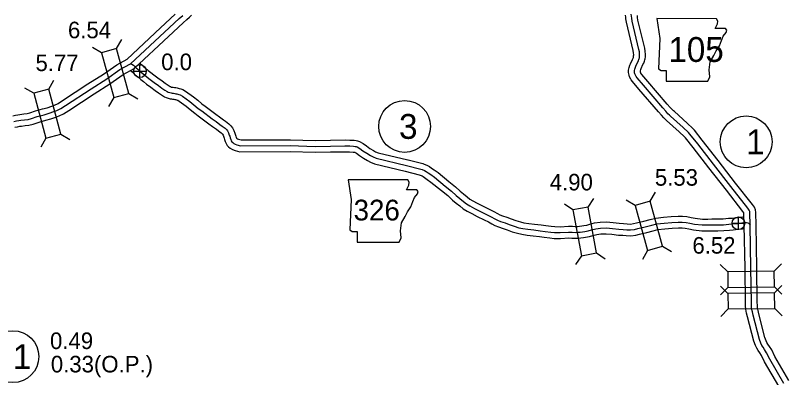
# Model space of a CAD drawing. Extents: x 31699 to 244310, y -8841 to 11474.
# Drawn here: x 97253 to 98557, y 4320 to 4936 of the extents above; entities that cross this region are included whole.
import ezdxf

# ---------------------------------------------------------------- set-up
doc = ezdxf.new("R2010")
doc.units = 0
for name, color, linetype in [('B_Logo', 7, 'Continuous'), ('G-ANNO-TEXT', 7, 'Continuous'), ('Level 21', 7, 'Continuous'), ('R_Border Notes', 7, 'Continuous'), ('R_XS_EARTHWORK_STAGE1', 7, 'Continuous'), ('R_XS_EARTHWORK_STAGE2', 7, 'Continuous'), ('S_WALL', 7, 'Continuous'), ('S_WALL_ANNOT', 7, 'Continuous')]:
    doc.layers.add(name, color=color, linetype=linetype)

msp = doc.modelspace()

# ---------------------------------------------------------------- linework, layer by layer
at = {"layer": 'B_Logo'}
for points in [[(97250.1, 4755.6), (97254.7, 4756.5), (97258.7, 4757.3), (97261.9, 4757.8), (97268.4, 4758.7), (97274.4, 4759.1), (97280.3, 4760.5), (97289.8, 4764), (97301.7, 4767.2), (97310, 4769.5), (97318, 4772.3), (97323.2, 4774.4), (97330, 4777.4), (97338.1, 4782.7), (97381.5, 4811), (97407.9, 4827.8), (97430.5, 4843.7), (97448.4, 4853.6), (97506.1, 4907.4), (97531.3, 4930.6), (97537.2, 4935.9)], [(98300.2, 4934.6), (98299.7, 4937.8)], [(98559.1, 4310.6), (98535.1, 4351.8), (98529.7, 4362.6), (98526.4, 4368), (98523.7, 4372.1), (98521.7, 4375.3), (98519.8, 4378.9), (98517.4, 4385.4), (98506.9, 4426.4), (98505.5, 4432.1), (98504.3, 4437.8), (98504.1, 4442.3), (98503.8, 4448.1), (98503.1, 4506.6), (98501.8, 4579.3), (98501.3, 4600.5), (98501, 4602.8), (98500.1, 4605), (98497.6, 4608.6), (98469.2, 4644.9), (98439.4, 4683.3), (98412.6, 4717.6), (98399.4, 4734.2), (98397, 4736.8), (98387.9, 4745.2), (98366.3, 4764.8), (98364.6, 4766.4), (98362, 4768.8), (98358.5, 4772.9), (98353.3, 4778.7), (98320.2, 4817.3), (98309.5, 4829.7), (98307.9, 4832.1), (98307.3, 4832.9), (98306.1, 4835.3), (98305.6, 4836.8), (98305.4, 4838.2), (98305.2, 4839.7), (98305, 4842.2), (98305.5, 4844.6), (98306.7, 4847.8), (98307.5, 4849.6), (98310.6, 4856.7), (98311.7, 4858.8), (98312.7, 4861.2), (98313.1, 4862.9), (98313.4, 4863.9), (98313.7, 4866.5), (98313.9, 4869), (98313.4, 4873.7), (98312.7, 4878.1), (98301.2, 4925.9), (98300.6, 4931.1), (98300.2, 4934.6)], [(97448.4, 4853.6), (97450.7, 4852.8), (97453.3, 4851.4), (97455.2, 4849.8), (97458.1, 4847), (97460.8, 4844.5), (97463.1, 4842.1), (97467, 4839), (97472.3, 4834.7), (97476.7, 4831.1), (97481.9, 4827), (97488.8, 4821.9), (97496.2, 4816.5), (97501.8, 4812.5), (97506.7, 4809), (97510.9, 4806.3), (97512.6, 4805.5), (97515.4, 4804.6), (97517.4, 4804.1), (97519.4, 4803.9), (97521.5, 4803.5), (97523.5, 4803.2), (97525.5, 4802.8), (97527, 4802.5), (97528.9, 4802), (97530.8, 4801.6), (97533.1, 4800.7), (97536.6, 4798.8), (97549.4, 4789.5), (97556.2, 4783.9), (97563.6, 4777.9), (97569.4, 4773.5), (97587.5, 4759.9), (97593.8, 4755.4), (97600.5, 4750.6), (97604.1, 4747.9), (97609.1, 4744.1), (97611.6, 4741.8), (97613.4, 4739.5), (97615, 4736.5), (97616.3, 4732.6), (97617, 4730.9), (97617.9, 4728), (97618.8, 4724.9), (97619.6, 4723), (97620.7, 4721.3), (97622.1, 4719.8), (97623.8, 4718.3), (97626.2, 4716.8), (97629.3, 4715.7), (97635.5, 4714.2), (97720.1, 4714.7), (97762.3, 4713.4), (97788.4, 4713.8), (97813, 4714.2), (97821.1, 4714.1), (97827.6, 4713.6), (97830.4, 4713.3), (97832.1, 4713), (97834, 4712.5), (97838.4, 4710), (97843.5, 4705.9), (97850.1, 4701.6), (97856.3, 4697.7), (97860.7, 4695.3), (97866.1, 4693.1), (97917.8, 4681)], [(97917.8, 4681), (97942.2, 4674.6), (97944.3, 4673.9), (97948.4, 4672.2), (97951.3, 4670.9), (97954.2, 4668.5), (97958.7, 4665.3), (97965.1, 4660.8), (97983.4, 4645.9), (97994.1, 4637.2), (98002.3, 4629.6), (98008.3, 4624.9), (98014.5, 4619.8), (98019.5, 4615.5), (98025.5, 4612.1), (98033.2, 4607.9), (98042.4, 4603.2), (98053.8, 4597.8), (98061.5, 4593.8), (98067.7, 4590.5), (98072.2, 4588.1), (98077.5, 4585.9), (98085.1, 4583.4), (98092, 4580.7), (98100.5, 4577.9), (98108.8, 4575.2), (98115.3, 4573.7), (98124.1, 4572.5), (98134.1, 4571.5), (98145.1, 4569.9), (98153.1, 4568.9), (98162.7, 4567.7), (98169.1, 4567), (98179, 4566.9), (98193.2, 4567.7), (98199, 4567.5), (98204.3, 4567.2), (98209.4, 4567.3), (98212.8, 4567.6), (98217, 4568.4), (98220.6, 4568.8), (98226.5, 4569.9), (98231.8, 4571.4), (98239.3, 4573.5), (98247.4, 4574.6), (98257.4, 4574.9), (98267.8, 4573.9), (98278.5, 4572.6), (98286.1, 4572.3), (98291.9, 4571.8), (98298.4, 4571.3), (98305.4, 4572.2), (98311.1, 4573.6), (98323.4, 4576.6), (98334.4, 4579.6), (98343.1, 4581.7), (98355.7, 4583), (98368.5, 4584.1), (98379.5, 4584.8), (98386.4, 4584.7), (98392.8, 4584.2), (98399.5, 4582.9), (98406.9, 4581.4), (98420.3, 4579.9), (98429.7, 4579.9), (98436.8, 4580), (98446.6, 4580), (98456.4, 4580.3), (98465.5, 4581.2), (98471.9, 4581.7), (98476.1, 4582.1), (98481.4, 4582.5), (98484.7, 4583), (98487.4, 4583.3), (98490.5, 4583.7), (98492.6, 4583.8), (98494.3, 4583.9), (98495.7, 4583.9), (98497.7, 4583.5), (98498.8, 4582.9), (98499.7, 4582.4), (98500.3, 4581.5), (98500.8, 4581), (98501.8, 4579.3)]]:
    msp.add_lwpolyline(points, dxfattribs=at)
at = {"layer": 'G-ANNO-TEXT'}
for points in [[(98343, 4930.3), (98348.1, 4896.5), (98345.8, 4845.1), (98350.4, 4842.3), (98358.8, 4842.3), (98358.8, 4824.3), (98429.9, 4824.3), (98433.3, 4831.6), (98432.1, 4843.4), (98433.8, 4857), (98440, 4867.7), (98444, 4875.6), (98449.6, 4884.1), (98453, 4893.1), (98455.8, 4900.4), (98460.9, 4906.6), (98462, 4910.6), (98459.8, 4913.4), (98442.3, 4913.4), (98446.2, 4921.3), (98446.8, 4926.3), (98444.4, 4930.2)], [(97818.2, 4656.6), (97823.3, 4622.8), (97821, 4571.5), (97825.5, 4568.6), (97834, 4568.6), (97834, 4550.6), (97905, 4550.6), (97908.4, 4557.9), (97907.3, 4569.8), (97909, 4583.3), (97915.2, 4594), (97919.1, 4601.9), (97924.8, 4610.4), (97928.2, 4619.4), (97931, 4626.7), (97936.1, 4632.9), (97937.2, 4636.9), (97934.9, 4639.7), (97917.5, 4639.7), (97921.4, 4647.6), (97922, 4652.7), (97919.6, 4656.6)]]:
    msp.add_lwpolyline(points, close=True, dxfattribs=at)
at = {"layer": 'Level 21'}
for p, q in [((97453.5, 4841.1), (97475.2, 4841.1)), ((97464.4, 4830.2), (97464.4, 4851.9)), ((98481.8, 4572), (98481.8, 4593.7)), ((98470.9, 4582.8), (98492.6, 4582.8))]:
    msp.add_line(p, q, dxfattribs=at)
for centre in [(97464.4, 4841.1), (98481.8, 4582.8)]:
    msp.add_circle(centre, 10.8, dxfattribs=at)
at = {"layer": 'R_Border Notes'}
for centre in [(97914.4, 4747.2), (98495, 4721), (97248.6, 4356.1)]:
    msp.add_circle(centre, 44, dxfattribs=at)
at = {"layer": 'R_XS_EARTHWORK_STAGE1'}
for p, q in [((97424.6, 4879.4), (97433.4, 4894.7)), ((97399.2, 4872.5), (97383.9, 4881.3)), ((97309.5, 4810.4), (97318.2, 4825.6)), ((97284, 4803.5), (97268.7, 4812.2)), ((97445.3, 4803), (97460.6, 4794.2)), ((97419.9, 4796.1), (97411.1, 4780.8)), ((97304.7, 4727), (97295.9, 4711.8)), ((97330.2, 4733.9), (97345.4, 4725.2)), ((98331.9, 4620), (98340.6, 4635.3)), ((98226.3, 4610.1), (98236.3, 4624.7)), ((98306.5, 4613), (98291.2, 4621.7)), ((98200.4, 4605.3), (98185.9, 4615.2)), ((98352.8, 4543.6), (98368.1, 4534.9)), ((98214.9, 4527.4), (98204.9, 4512.9)), ((98240.8, 4532.3), (98255.4, 4522.3)), ((98327.4, 4536.6), (98318.6, 4521.3)), ((98542.8, 4501.1), (98555.1, 4513.7)), ((98463.6, 4500.2), (98451, 4512.5)), ((98464, 4463.5), (98451.4, 4475.8)), ((98543.1, 4474.7), (98555.7, 4462.4)), ((98543.2, 4464.4), (98555.5, 4477)), ((98463.9, 4473.8), (98451.6, 4461.2)), ((98464.3, 4437.1), (98452, 4424.5)), ((98543.5, 4438), (98556.1, 4425.7))]:
    msp.add_line(p, q, dxfattribs=at)
for points in [[(97399.2, 4872.5), (97419.9, 4796.1), (97445.3, 4803), (97424.6, 4879.4)], [(97284, 4803.5), (97304.7, 4727), (97330.2, 4733.9), (97309.5, 4810.4)], [(98306.5, 4613), (98327.4, 4536.6), (98352.8, 4543.6), (98331.9, 4620)], [(98240.8, 4532.3), (98226.3, 4610.1), (98200.4, 4605.3), (98214.9, 4527.4)], [(98463.9, 4473.8), (98543.1, 4474.7), (98542.8, 4501.1), (98463.6, 4500.2)], [(98543.2, 4464.4), (98464, 4463.5), (98464.3, 4437.1), (98543.5, 4438)]]:
    msp.add_lwpolyline(points, close=True, dxfattribs=at)
at = {"layer": 'R_XS_EARTHWORK_STAGE2'}
for points in [[(97248.2, 4765.4), (97252.8, 4766.3), (97257, 4767.1), (97260.3, 4767.7), (97267.3, 4768.7), (97272.9, 4769.1), (97277.5, 4770.1), (97286.7, 4773.5), (97299, 4776.9), (97307, 4779), (97314.5, 4781.7), (97319.4, 4783.6), (97325.2, 4786.2), (97332.7, 4791.1), (97376.1, 4819.4), (97402.4, 4836.1), (97425.2, 4852.1), (97442.5, 4861.7), (97499.3, 4914.7), (97524.6, 4938.1)], [(97252, 4745.8), (97256.6, 4746.7), (97260.5, 4747.4), (97263.4, 4747.9), (97269.4, 4748.8), (97275.8, 4749.2), (97283.2, 4750.9), (97292.9, 4754.5), (97304.3, 4757.6), (97312.9, 4759.9), (97321.5, 4763), (97327.1, 4765.2), (97334.7, 4768.5), (97343.6, 4774.4), (97386.9, 4802.6), (97413.5, 4819.5), (97435.8, 4835.2), (97454.4, 4845.4), (97512.9, 4900.1), (97538, 4923.2), (97544, 4928.6), (97548.5, 4932.8), (97552.2, 4936)], [(98290.3, 4933), (98289.7, 4936.5)], [(98550.4, 4305.7), (98526.2, 4347.1), (98521, 4357.8), (98518, 4362.6), (98515.2, 4366.7), (98513, 4370.3), (98510.6, 4374.9), (98507.9, 4382.5), (98497.2, 4424), (98495.8, 4429.9), (98494.4, 4436.5), (98494.1, 4441.8), (98493.8, 4447.8), (98493.1, 4506.5), (98491.8, 4579.1), (98491.3, 4599.9), (98491.3, 4600.2), (98489.6, 4602.7), (98461.3, 4638.7), (98431.5, 4677.1), (98404.7, 4711.5), (98391.8, 4727.7), (98390, 4729.7), (98381.1, 4737.9), (98359.6, 4757.4), (98357.9, 4759), (98354.8, 4761.8), (98351, 4766.3), (98345.8, 4772.1), (98312.6, 4810.8), (98301.5, 4823.7), (98299.7, 4826.4), (98298.8, 4827.6), (98296.8, 4831.6), (98295.9, 4834.5), (98295.5, 4836.6), (98295.2, 4838.6), (98294.9, 4842.8), (98295.9, 4847.4), (98297.4, 4851.5), (98298.3, 4853.6), (98301.6, 4861.1), (98302.7, 4863.1), (98303.2, 4864.3), (98303.5, 4865.5), (98303.6, 4865.9), (98303.7, 4867.4), (98303.8, 4868.8), (98303.5, 4872.4), (98302.9, 4876.1), (98291.3, 4924.1), (98290.6, 4929.9), (98290.2, 4933.4)], [(98567.8, 4315.4), (98543.9, 4356.6), (98538.5, 4367.5), (98534.8, 4373.4), (98532.1, 4377.5), (98530.3, 4380.3), (98528.9, 4383), (98527, 4388.4), (98516.6, 4428.8), (98515.3, 4434.3), (98514.3, 4439.1), (98514.1, 4442.8), (98513.8, 4448.4), (98513.1, 4506.8), (98511.8, 4579.5), (98511.3, 4601.2), (98510.8, 4605.4), (98508.9, 4609.9), (98505.7, 4614.5), (98477.1, 4651), (98447.3, 4689.4), (98420.4, 4723.8), (98407, 4740.7), (98404.1, 4743.9), (98394.7, 4752.6), (98373, 4772.3), (98371.3, 4773.8), (98369.2, 4775.7), (98366, 4779.5), (98360.8, 4785.3), (98327.8, 4823.8), (98317.5, 4835.7), (98316.1, 4837.9), (98315.8, 4838.3), (98315.4, 4839.1), (98315.4, 4839.2), (98315.3, 4839.7), (98315.1, 4840.8), (98315.1, 4841.5), (98315.1, 4841.9), (98316, 4844.1), (98316.7, 4845.7), (98319.6, 4852.4), (98320.8, 4854.6), (98322.3, 4858.2), (98322.8, 4860.2), (98323.3, 4861.8), (98323.7, 4865.7), (98323.9, 4869.2), (98323.3, 4875.1), (98322.5, 4880.1), (98311.1, 4927.7), (98310.5, 4932.3), (98310.1, 4935.7)], [(97464.7, 4854.6), (97465, 4854.3), (97467.9, 4851.6), (97469.8, 4849.5), (97473.3, 4846.8), (97478.6, 4842.4), (97483, 4838.9), (97487.9, 4834.9), (97494.7, 4830), (97502, 4824.7), (97507.6, 4820.7), (97512.4, 4817.3), (97515.7, 4815.1), (97516.3, 4814.9), (97518.2, 4814.2), (97519.1, 4814), (97520.8, 4813.8), (97523.1, 4813.4), (97525.2, 4813.1), (97527.5, 4812.7), (97529.3, 4812.3), (97531.3, 4811.7), (97533.7, 4811.2), (97537.2, 4809.9), (97542, 4807.2), (97555.6, 4797.4), (97562.6, 4791.6), (97569.8, 4785.8), (97575.5, 4781.5), (97593.4, 4767.9), (97599.6, 4763.5), (97606.3, 4758.6), (97610, 4756), (97615.7, 4751.7), (97619, 4748.5), (97621.7, 4745.1), (97624.3, 4740.5), (97625.7, 4736), (97626.4, 4734.2), (97627.4, 4730.9), (97628.2, 4728.3), (97628.4, 4727.8), (97628.6, 4727.5), (97629.1, 4726.9), (97629.8, 4726.4), (97630.5, 4725.9), (97632.1, 4725.3), (97636.7, 4724.2), (97720.2, 4724.7), (97762.4, 4723.4), (97788.2, 4723.8), (97813.1, 4724.2), (97821.5, 4724.1), (97828.5, 4723.6), (97831.9, 4723.2), (97834.3, 4722.8), (97837.8, 4721.8), (97844, 4718.3), (97849.4, 4714), (97855.5, 4710), (97861.3, 4706.4), (97865.1, 4704.3), (97869.2, 4702.6), (97920.1, 4690.7)], [(97448.6, 4842.3), (97451.2, 4839.8), (97453.8, 4837.4), (97456.4, 4834.7), (97460.7, 4831.2), (97466, 4826.9), (97470.4, 4823.3), (97475.8, 4819), (97482.9, 4813.8), (97490.3, 4808.4), (97496, 4804.4), (97501.1, 4800.7), (97506.1, 4797.5), (97509, 4796.2), (97512.7, 4795), (97515.7, 4794.3), (97517.9, 4794), (97519.9, 4793.7), (97521.8, 4793.4), (97523.5, 4793), (97524.7, 4792.8), (97526.5, 4792.3), (97527.9, 4792), (97528.9, 4791.6), (97531.2, 4790.3), (97543.3, 4781.6), (97549.9, 4776.1), (97557.5, 4770), (97563.4, 4765.5), (97581.6, 4751.8), (97588, 4747.3), (97594.6, 4742.5), (97598.1, 4739.9), (97602.6, 4736.5), (97604.2, 4735), (97605, 4733.9), (97605.8, 4732.6), (97606.8, 4729.2), (97607.5, 4727.5), (97608.3, 4725.1), (97609.3, 4721.5), (97610.8, 4718.1), (97612.9, 4715.1), (97615.1, 4712.7), (97617.9, 4710.2), (97621.9, 4707.8), (97626.4, 4706.2), (97634.3, 4704.2), (97720, 4704.7), (97762.3, 4703.4), (97788.5, 4703.8), (97813, 4704.2), (97820.7, 4704.1), (97826.8, 4703.7), (97829, 4703.4), (97829.9, 4703.3), (97830.2, 4703.2), (97832.8, 4701.7), (97837.6, 4697.9), (97844.7, 4693.1), (97851.3, 4689.1), (97856.4, 4686.3), (97863, 4683.5), (97915.5, 4671.2)], [(97920.3, 4690.6), (97945.2, 4684.2), (97947.9, 4683.2), (97952.4, 4681.4), (97956.6, 4679.4), (97960.2, 4676.5), (97964.5, 4673.5), (97971.2, 4668.7), (97989.7, 4653.6), (98000.7, 4644.7), (98008.7, 4637.2), (98014.6, 4632.7), (98021, 4627.4), (98025.2, 4623.7), (98030.4, 4620.8), (98037.8, 4616.8), (98046.8, 4612.1), (98058.3, 4606.7), (98066.2, 4602.6), (98072.4, 4599.3), (98076.4, 4597.1), (98081, 4595.3), (98088.4, 4592.8), (98095.4, 4590.1), (98103.6, 4587.4), (98111.5, 4584.9), (98117.1, 4583.6), (98125.3, 4582.5), (98135.4, 4581.4), (98146.5, 4579.8), (98154.3, 4578.8), (98163.8, 4577.7), (98169.7, 4577), (98178.8, 4576.9), (98193, 4577.7), (98199.5, 4577.5), (98204.5, 4577.2), (98208.8, 4577.3), (98211.5, 4577.6), (98215.6, 4578.3), (98219.1, 4578.7), (98224.2, 4579.6), (98229.1, 4581), (98237.2, 4583.3), (98246.6, 4584.6), (98257.7, 4584.9), (98268.9, 4583.9), (98279.3, 4582.6), (98286.7, 4582.3), (98292.7, 4581.8), (98298.1, 4581.4), (98303.6, 4582.1), (98308.7, 4583.3), (98320.9, 4586.3), (98331.8, 4589.3), (98341.4, 4591.6), (98354.7, 4592.9), (98367.7, 4594.1), (98379.3, 4594.8), (98386.9, 4594.7), (98394.2, 4594.1), (98401.4, 4592.7), (98408.5, 4591.3), (98420.8, 4589.9), (98429.6, 4589.9), (98436.8, 4590), (98446.5, 4590), (98455.8, 4590.3), (98464.7, 4591.1), (98471, 4591.6), (98475.2, 4592), (98480.3, 4592.5), (98483.4, 4592.9), (98486.2, 4593.2), (98489.6, 4593.6), (98491.3, 4593.7)], [(97915.3, 4671.3), (97939.2, 4665.1), (97940.7, 4664.6), (97944.4, 4663.1), (97946, 4662.3), (97948.2, 4660.5), (97952.9, 4657.2), (97959.1, 4652.8), (97977.1, 4638.1), (97987.6, 4629.6), (97995.8, 4622), (98002.1, 4617.1), (98008.1, 4612.1), (98013.7, 4607.3), (98020.7, 4603.3), (98028.5, 4599.1), (98037.9, 4594.2), (98049.4, 4588.8), (98056.9, 4584.9), (98062.9, 4581.6), (98067.9, 4579), (98074.1, 4576.5), (98081.7, 4574), (98088.6, 4571.3), (98097.4, 4568.4), (98106.2, 4565.6), (98113.5, 4563.9), (98122.9, 4562.6), (98132.9, 4561.6), (98143.8, 4560), (98151.9, 4559), (98161.5, 4557.8), (98168.4, 4557), (98179.3, 4556.9), (98193.3, 4557.7), (98198.5, 4557.6), (98204.1, 4557.2), (98210.1, 4557.3), (98214.2, 4557.7), (98218.4, 4558.5), (98222.1, 4558.9), (98228.8, 4560.1), (98234.5, 4561.8), (98241.3, 4563.7), (98248.2, 4564.6), (98257.1, 4564.9), (98266.7, 4564), (98277.7, 4562.6), (98285.5, 4562.3), (98291.1, 4561.8), (98298.7, 4561.3), (98307.3, 4562.4), (98313.4, 4563.9), (98325.9, 4566.9), (98336.9, 4569.9), (98344.7, 4571.9), (98356.6, 4573), (98369.3, 4574.1), (98379.7, 4574.8), (98386, 4574.7), (98391.5, 4574.3), (98397.6, 4573.1), (98405.4, 4571.6), (98419.7, 4569.9), (98429.8, 4569.9), (98436.9, 4570), (98446.7, 4570), (98457.1, 4570.3), (98466.4, 4571.2), (98472.8, 4571.7), (98477, 4572.1), (98482.4, 4572.6), (98485.9, 4573), (98488.6, 4573.4), (98491.3, 4573.7), (98491.8, 4573.7)]]:
    msp.add_lwpolyline(points, dxfattribs=at)

# ---------------------------------------------------------------- texts
at = {"layer": 'G-ANNO-TEXT'}
for s, height, p in [('105', 42.24, (98362.7, 4856.8)), ('326', 35.2, (97827.7, 4587.5))]:
    msp.add_text(s, height=height, dxfattribs=at).set_placement(p)
at = {"layer": 'R_Border Notes'}
for s, p in [('3', (97904.9, 4726.1)), ('1', (98495, 4699.9)), ('1', (97248.6, 4334.9))]:
    msp.add_text(s, height=42.2, dxfattribs=at).set_placement(p)
at = {"layer": 'S_WALL'}
for s, p in [('6.54', (97342.1, 4897)), ('5.77', (97286.9, 4841.2)), ('5.53', (98339.8, 4646.5)), ('4.90', (98161.1, 4638.5)), ('0.33(O.P.)', (97313, 4329.3))]:
    msp.add_text(s, height=28.16, dxfattribs=at).set_placement(p)
at = {"layer": 'S_WALL_ANNOT'}
for s, p in [('0.0', (97500.6, 4842.8)), ('6.52', (98403.6, 4531.1)), ('0.49', (97311.6, 4369))]:
    msp.add_text(s, height=28.16, dxfattribs=at).set_placement(p)

doc.saveas('drawing.dxf')
